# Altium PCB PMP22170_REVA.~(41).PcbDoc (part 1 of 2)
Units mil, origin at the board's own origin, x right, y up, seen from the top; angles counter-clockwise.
Board outline 4950 x 3450 mil, 2 copper layers (Top Layer, Bottom Layer), stack 62 mil thick; 75 components, 28 nets, 158 pads, 70 vias.
Unrouted connection lines stored in the file: 122.
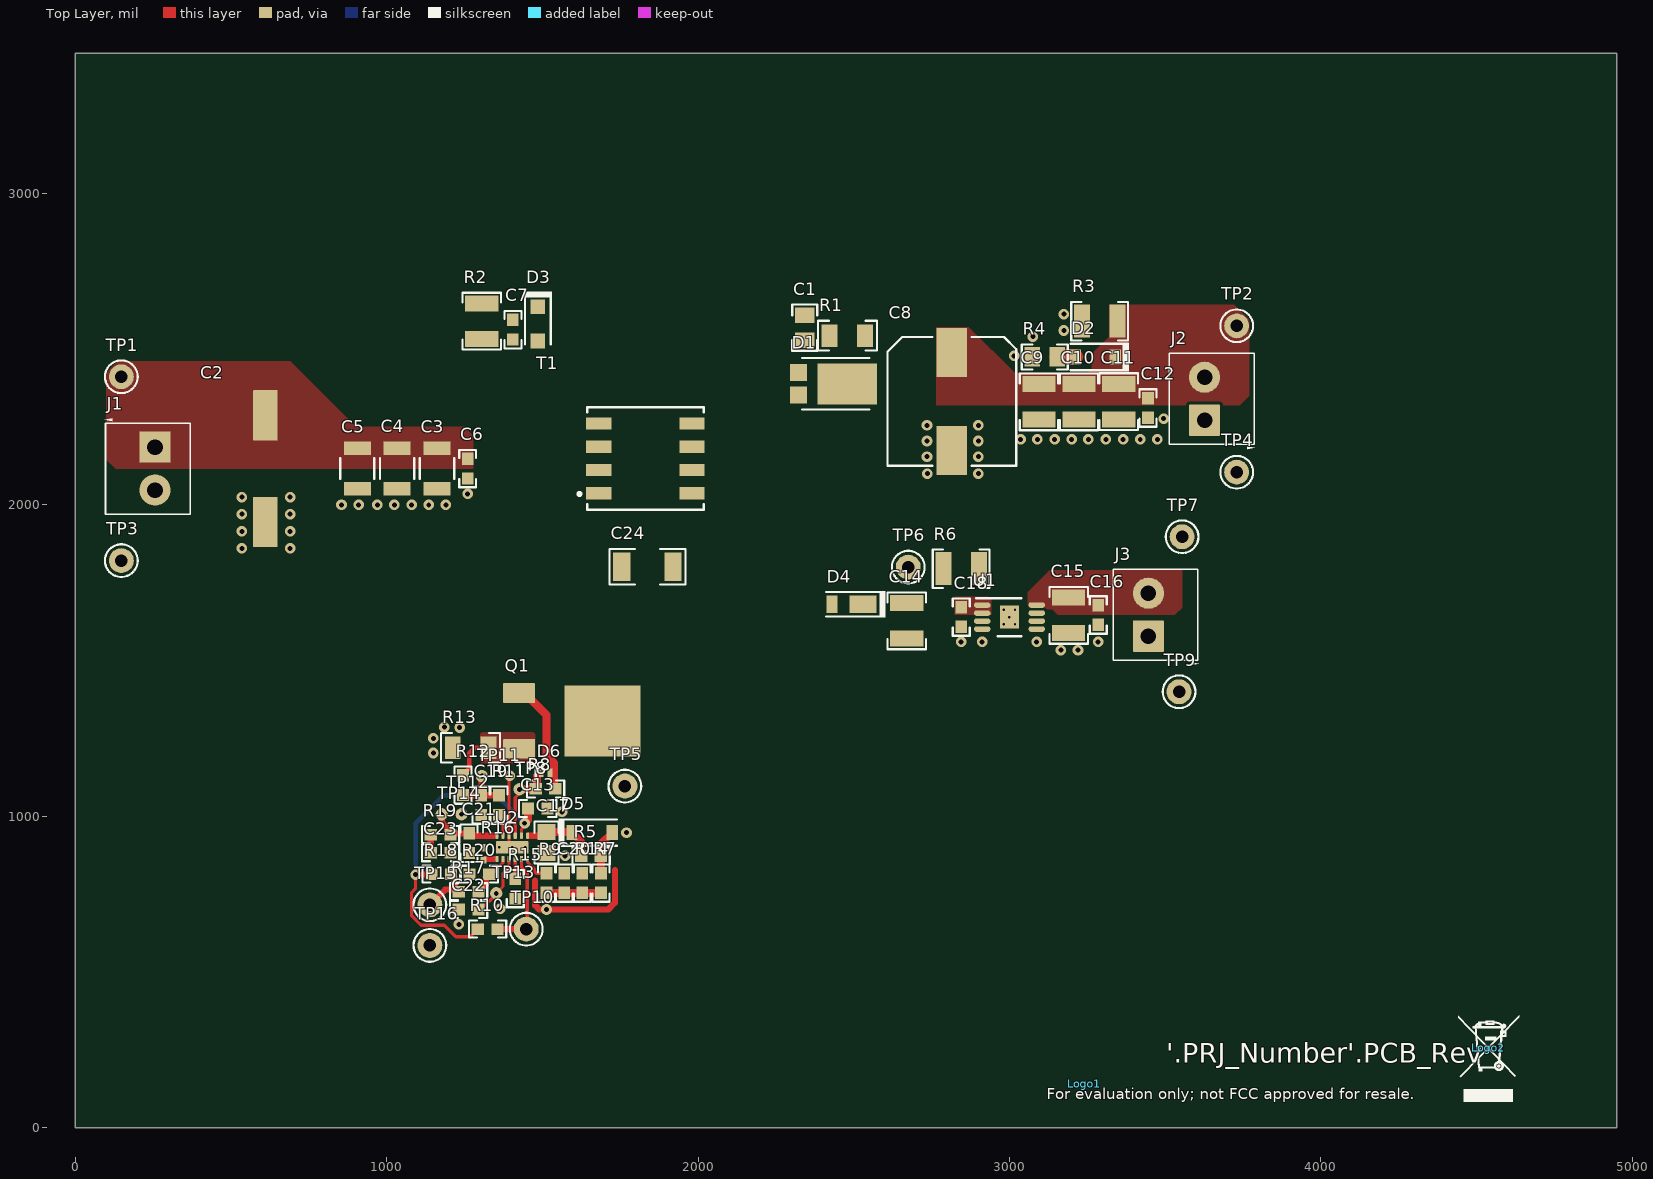
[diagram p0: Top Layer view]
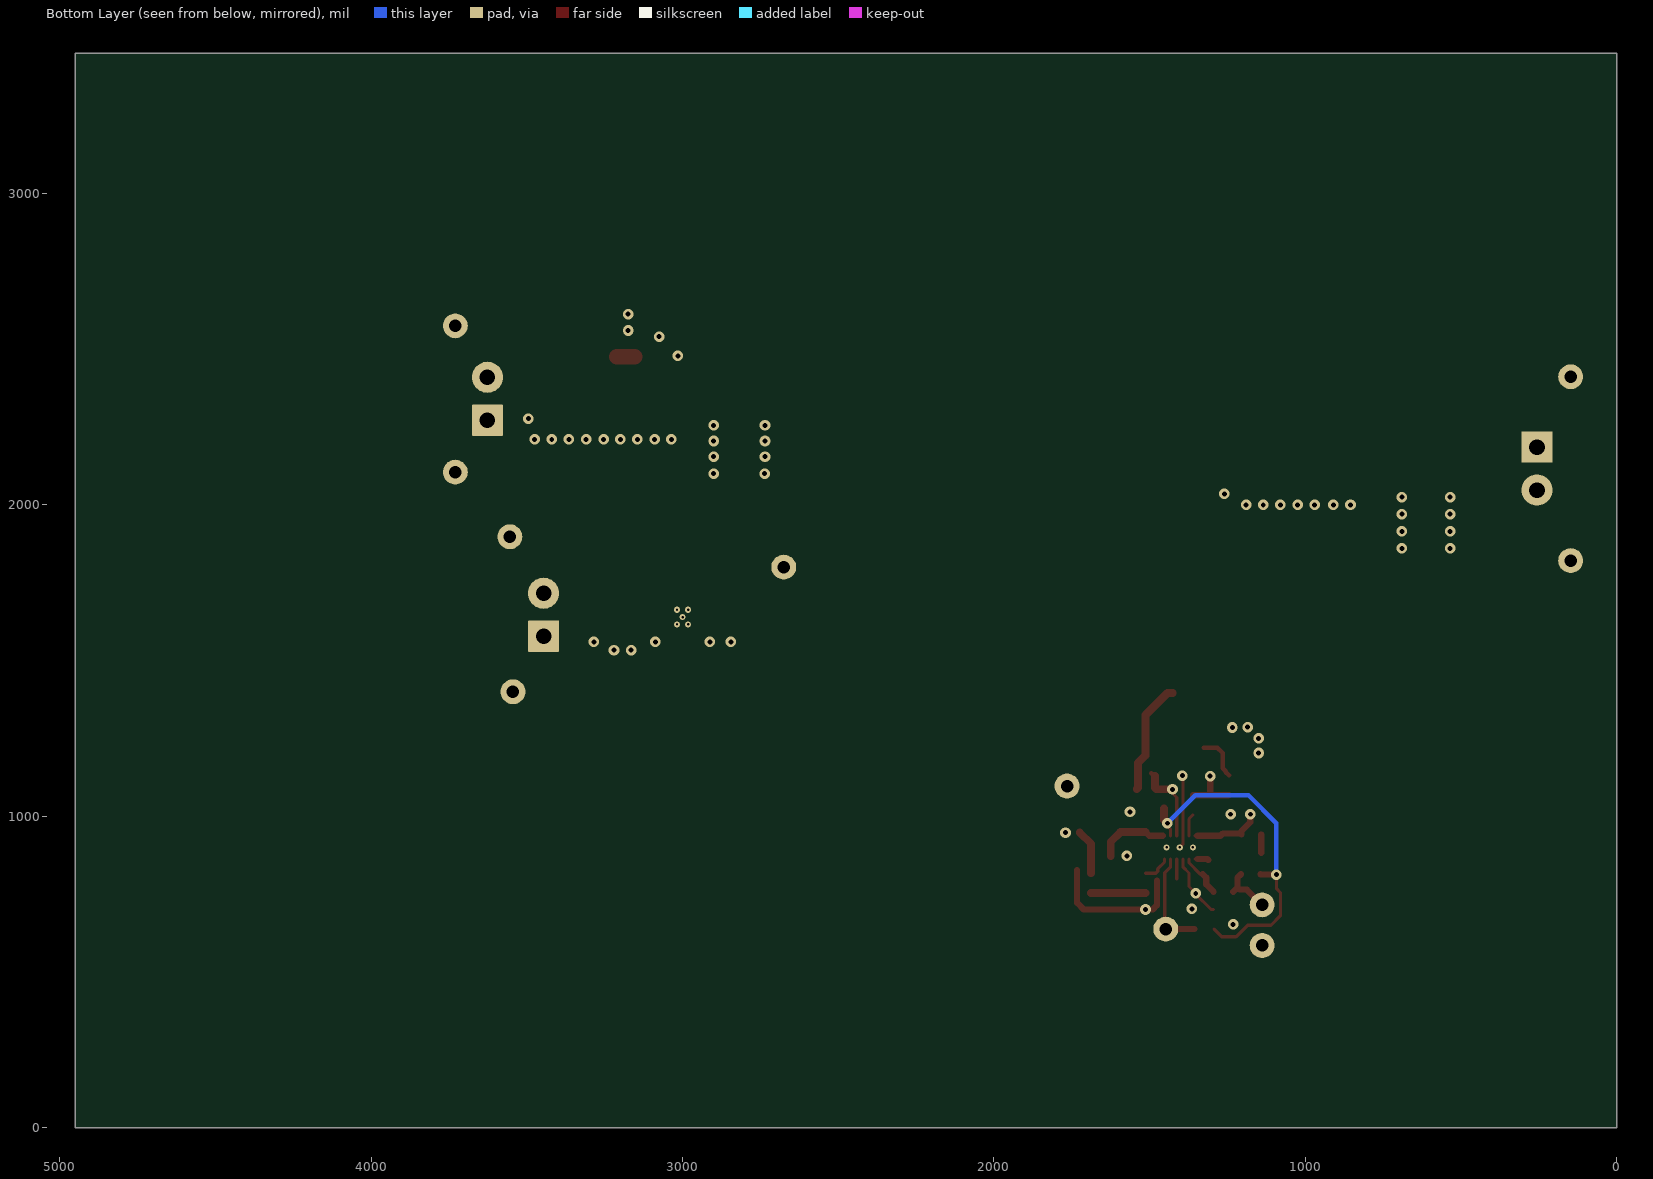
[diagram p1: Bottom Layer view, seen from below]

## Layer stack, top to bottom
Top Solder: solder mask 0.4, Solder Resist, Dk 3.5
Top Layer: signal copper 1.4
Dielectric1: core 59.2, FR-4, Dk 4.8
Bottom Layer: signal copper 1.4
Bottom Solder: solder mask 0.4, Solder Resist, Dk 3.5

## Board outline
0,0 4950,0 4950,3450 0,3450

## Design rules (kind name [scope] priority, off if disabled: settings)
AcuteAngle [All] p1: minimum=4.50000000000000E+0001 checktracksonly=FALSE
AssemblyTestPointUsage [All] p1: valid=2
BoardOutlineClearance BoardOutlineClearance_MountingHoles [OnCopper and InComponentClass('Mounting Holes')] p1: gap=39.37 ignorepadtopadclearanceinfootprint=FALSE
BoardOutlineClearance BoardOutlineClearance_Poly [OnCopper and IsPoly] p2: gap=25 ignorepadtopadclearanceinfootprint=FALSE
BoardOutlineClearance [OnCopper and Not InComponentClass('Logo') and not InComponentClass('FiducialMark') and not InRegion(1000,500,4000,800) and not InPoly] p3: gap=50 ignorepadtopadclearanceinfootprint=FALSE
Clearance Clearance_Keepouts [((IsTrack Or IsArc) And Not InPoly) And IsFree and IsKeepOut vs ((IsTrack Or IsArc) And Not InPoly) And IsFree and IsKeepOut] p1: gap=0 ignorepadtopadclearanceinfootprint=FALSE
Clearance Clearance_Poly [InPolygon] p2: gap=10 ignorepadtopadclearanceinfootprint=TRUE
Clearance Clearance_FiducialMark [IsKeepOut and InComponentClass('FiducialMark') vs IsPad and InComponentClass('FiducialMark')] p3: gap=0 ignorepadtopadclearanceinfootprint=FALSE
Clearance [All] p4: gap=7.87 ignorepadtopadclearanceinfootprint=TRUE
ComponentClearance ComponentClearance_MountingHoles_FiducialMarks [InComponentClass('Mounting Holes') vs InComponentClass('FiducialMark')] p1: gap=50 collisioncheckmode=3 verticalgap=10 showdistances=FALSE
ComponentClearance ComponentClearance_Shunt [InComponentClass('Header') vs InComponentClass('Shunt')] p2: gap=0 collisioncheckmode=3 verticalgap=0 showdistances=FALSE
ComponentClearance ComponentClearance_Logo [InComponentClass('Logo')] p3: gap=50 collisioncheckmode=3 verticalgap=10 showdistances=FALSE
ComponentClearance ComponentClearance_ScrewToNut [(HasFootprint('NY PMS 440 0025 PH')) vs (HasFootprint('Keystone_1902C'))] p4: gap=5 collisioncheckmode=3 verticalgap=10 showdistances=FALSE
ComponentClearance ComponentClearance_MountingHoles [InComponentClass('Mounting Holes')] p5: gap=250 collisioncheckmode=3 verticalgap=100000 showdistances=FALSE
ComponentClearance ComponentClearance_SmallPassives [HasFootprint('0201*') or HasFootprint('0402*') or HasFootprint('0508') or HasFootprint('0603*') or HasFootprint('0612') or HasFootprint('0805*') or HasFootprint('0815*') or HasFootprint('0830*') or HasFootprint('1206*') or HasFootprint('1210*') or HasFootprint('1808*') or HasFootprint('1812*') or HasFootprint('1825*') or HasFootprint('2010*') or HasFootprint('2220*') or HasFootprint('2225*') or HasFootprint('2512*') or HasFootprint('2728*') or HasFootprint('3518*') vs HasFootprint('0201*') or HasFootprint('0402*') or HasFootprint('0508') or HasFootprint('0603*') or HasFootprint('0612') or HasFootprint('0805*') or HasFootprint('0815*') or HasFootprint('0830*') or HasFootprint('1206*') or HasFootprint('1210*') or HasFootprint('1808*') or HasFootprint('1812*') or HasFootprint('1825*') or HasFootprint('2010*') or HasFootprint('2220*') or HasFootprint('2225*') or HasFootprint('2512*') or HasFootprint('2728*') or HasFootprint('3518*')] p6: gap=14.96 collisioncheckmode=3 verticalgap=10 showdistances=FALSE
ComponentClearance ComponentClearance_THtoSMT [IsThruComponent vs IsSMTComponent] p7: gap=30 collisioncheckmode=3 verticalgap=30 showdistances=FALSE
ComponentClearance ComponentClearance_THtoTH [IsThruComponent vs IsThruComponent] p8: gap=30 collisioncheckmode=3 verticalgap=30 showdistances=FALSE
ComponentClearance [All] p9: gap=20 collisioncheckmode=3 verticalgap=10 showdistances=FALSE
DiffPairsRouting [All] p1: maxlimit=100 minlimit=10 mostfreqgap=10 toplayer_minwidth=15 toplayer_maxwidth=15 toplayer_prefwidth=15 bottomlayer_minwidth=15 bottomlayer_maxwidth=15 bottomlayer_prefwidth=15 maxuncoupledlength=1000
FabricationTestPointUsage TestPointUsage [All] p1: valid=2 allowmultiple=FALSE
FabricationTestpoint Testpoint [All] p1: side=3 testpointundercomponent=TRUE minsize=40 maxsize=100 preferedsize=60 minholesize=0 maxholesize=40 preferedholesize=32 testpointgrid=1 allowsidetop=TRUE allowsidebottom=TRUE usegrid=TRUE gridtolerance=0.01
FanoutControl Fanout_LCC [IsLCC] p1: bgadir=Out bgaviamode=Centered fanoutstyle=Auto fanoutdirection=Alternating viagrid=1 // Fanout_LCC (Default Rule)
FanoutControl Fanout_BGA [IsBGA] p2: bgadir=Out bgaviamode=Centered fanoutstyle=Auto fanoutdirection=Alternating viagrid=1 // Fanout_BGA (Default Rule)
FanoutControl Fanout_Default [All] p4: bgadir=Out bgaviamode=Centered fanoutstyle=Auto fanoutdirection=Alternating viagrid=1 // Fanout_Default (Default Rule)
FanoutControl Fanout_Small [(CompPinCount < 5)] p5: bgadir=Out bgaviamode=Centered fanoutstyle=Auto fanoutdirection=OutThenIn viagrid=1 // Fanout_Small (Default Rule)
HoleSize [All] p1: absolutevalues=TRUE maxlimit=251 minlimit=7.87 maxpercent=80.000 minpercent=20.000
MinimumAnnularRing MinimumAnnularRing_ThermalPadVias [IsVia and InAnyComponent] p1: minimumring=5.91
MinimumAnnularRing [All] p2: minimumring=7.87
MinimumSolderMaskSliver MinimumSolderMaskSliver_Logo [InComponentClass('Logo') vs InComponentClass('Logo')] p1: minsoldermaskwidth=0.7
MinimumSolderMaskSliver [All] p2: minsoldermaskwidth=3.94
PlaneClearance [All] p1: clearance=15
PlaneConnect [All] p1: planeconnectstyle=Direct reliefexpansion=10 reliefentries=4 reliefconductorwidth=10 reliefairgap=10
PolygonConnect [All] p1: connectstyle=Direct reliefconductorwidth=10 reliefentries=4 polygonreliefangle="90 Angle" airgapwidth=10
RoutingVias ThermalPadVias [IsVia and InAnyComponent] p1: holewidth=7.87 width=19.68 viastyle="Through Hole" minholewidth=7.87 minwidth=19.68 maxholewidth=12.99 maxwidth=23.62
RoutingVias [All] p2: holewidth=16 width=34 viastyle="Through Hole" minholewidth=7.87 minwidth=26 maxholewidth=40 maxwidth=65
SilkToBoardRegionClearance [Not ((IsComment or IsDesignator) And (Hide <> 'False')) and not InRegion(1000,500,4000,800)] p1:
SilkToSilkClearance SilkToSilkClearance_Pb-FreeLogo [(HasFootprint('Pb-Free_Overlay_Medium') OR HasFootprint('Pb-Free_Overlay_Small')) vs (HasFootprint('Pb-Free_Overlay_Medium') OR HasFootprint('Pb-Free_Overlay_Small'))] p1: silktosilkclearance=0
SilkToSilkClearance [All] p2: silktosilkclearance=0
SilkToSolderMaskClearance SilkToComponentPadClearance [(IsPad or IsFill or IsRegion) and InAnycomponent] p1: minsilkscreentomaskgap=5 clearancetoexposedcopper=TRUE
SilkToSolderMaskClearance "Silk to Solder Mask Opening" [All] p2: minsilkscreentomaskgap=0 clearancetoexposedcopper=FALSE
SolderMaskExpansion [All] p1: expansion=1.97
UnRoutedNet [All] p1: checkbadconnections=TRUE
Width [All] p1: maxlimit=100 minlimit=6 preferedwidth=10 checkconnectedcopper=TRUE
13 further rules are at their usual default settings.

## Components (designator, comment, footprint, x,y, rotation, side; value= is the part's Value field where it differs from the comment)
C1 "Capacitor" 0805_HV 2342.52,2568.9 r270 top value=100pF
C2 "EEH-ZS1H221V" FP-EEHZS1H221P_RADIAL_SMD-MFG 610.24,2116.35 r90 top
C3 "UMK325AB7106KMHT" 1210_280 1161.42,2116.35 r270 top value=10uF
C4 "UMK325AB7106KMHT" 1210_280 1033.46,2116.35 r270 top value=10uF
C5 "UMK325AB7106KMHT" 1210_280 905.51,2116.35 r270 top value=10uF
C6 "Capacitor" 0603 1259.84,2116.35 r270 top value=0.1uF
C7 "Capacitor" 0603 1405.32,2562.52 r90 top value=0.1uF
C8 "EEHZC1E331P" SM_RADIAL_10BMM 2814.96,2332.31 r270 top value=330uF
C9 "TMK325B7226KMHT" 1210_270 3095,2330.98 r270 top value=22uF
C10 "TMK325B7226KMHT" 1210_270 3222.95,2330.98 r270 top value=22uF
C11 "TMK325B7226KMHT" 1210_270 3350.91,2331.16 r270 top value=22uF
C12 "Capacitor" 0603 3445,2311.04 r270 top value=0.1uF
C13 "GCM188R71E105KA64D" 0603 1485,1025 r0 top value=1uF
C14 "Capacitor" 1210_270 2670,1627.56 r270 top value=22uF
C15 "Capacitor" 1210_270 3190,1645 r270 top value=47uF
C16 "Capacitor" 0603 3285,1646.26 r270 top value=0.1uF
C17 "Capacitor" 0805 1513.07,915.85 r270 top value=1uF
C18 "Capacitor" 0603 2845,1639.57 r270 top value=0.1uF
C19 "Capacitor" 0603 1303.03,1035.77 r270 top value=1000pF
C20 "Capacitor" 0603 1570.03,785.34 r90 top value=10pF
C21 "CGA3E2X7R2A222K080AA" 0603 1264.52,913.39 r270 top value=2200pF
C22 "Capacitor" 0603 1263.15,700.46 r180 top value=0.1uF
C23 "CGA3E3X7R1H334K080AB" 0603 1173.03,882.38 r0 top value=0.33uF
C24 "Capacitor" 1808 1837.24,1801.18 r180 top value=1000pF
D1 "PDS4200HQ-13" POWERDI5 2401.22,2388.58 r0 top value=200V
D2 "MMSZ5240B-7-F" SOD-123 3275.59,2475 r180 top value=10V
D3 "DIODE_SCHOTTKY" SOD-123W 1485.32,2581.22 r270 top value=100V
D4 "DFLS1200Q-7" PowerDI123 2479.8,1680.71 r180 top value=200V
D5 "SD103AW-7-F" SOD-123 1659.53,947.38 r0 top value=40V
D6 "DIODE_SCHOTTKY" X1-DFN1006-2 1510,1139.93 r0 top value=30V
J1 "Receptacle_2x1" TERM_BLK_ED555-2DS 255.91,2185.24 r270 top
J2 "Receptacle_2x1" TERM_BLK_ED555-2DS 3626.5,2271.67 r90 top
J3 "Receptacle_2x1" TERM_BLK_ED555-2DS 3446.18,1578.05 r90 top
Logo1 "FCC disclaimer" FCC_disclaimer 3240,140 r0 top
Logo2 "WEEE logo" WEEE_Minimum 4537.4,255.91 r0 top
Q1 "IPD60N10S4L12ATMA1" DPAK 1559.25,1305.91 r0 top value=100V
R1 "CRCW1206100RFKEAHP" 1206 2479.61,2543.31 r0 top value=100
R2 "ERJ14NF1001U" 1210 1305.32,2590 r270 top value=1.00k
R3 "ERJ14NF1001U" 1210 3289.76,2590 r0 top value=1.00k
R4 "CRCW080580R6FKEA" 0805_HV 3113.19,2475 r0 top value=80.6
R5 "Resistor" 0603 1656.22,872.38 r0 top value=0
R6 "ERJ14NF1001U" 1210 2845,1795 r180 top value=1.00k
R7 "CRCW0603100KFKEA" 0603 1688.07,785.34 r90 top value=100k
R8 "Resistor" 0603 1510,1087.68 r180 top value=10.0
R9 "CRCW060371K5FKEA" 0603 1513.03,785.34 r90 top value=71.5k
R10 "CRCW060310K0FKEA" 0603 1324.17,637.38 r0 top value=10.0k
R11 "Resistor" 0603 1360.71,1035.77 r90 top value=0
R12 "Resistor" 0603 1245,1100 r90 top value=100
R13 "ERJ-8BWFR010V" 1206 1269.19,1220 r0 top value=0.010
R14 "CRCW060324K9FKEA" 0603 1628.03,785.34 r270 top value=24.9k
R15 "CRCW060373K2FKEA" 0603 1412.87,767.38 r90 top value=73.2k
R16 "CRCW04020000Z0ED" 0402L 1311.38,878.94 r270 top value=0
R17 "Resistor" 0603 1263.03,757.38 r0 top value=6.04k
R18 "CRCW060320R0FKEA" 0603 1174.98,813.88 r180 top value=20.0
R19 "CRCW06033K01FKEA" 0603 1173.03,940.89 r0 top value=3.01k
R20 "CRCW06031K00FKEA" 0603 1297.6,813.88 r0 top value=1.00k
T1 "" WURTH_750312924 1830.71,2149.24 r90 top
TP1 "5000" Keystone5000 147.64,2411.42 r90 top
TP2 "5000" Keystone5000 3729.76,2575 r90 top
TP3 "5001" Keystone5001 147.64,1820.87 r90 top
TP4 "5001" Keystone5001 3729.76,2105 r90 top
TP5 "5002" Keystone5002 1765,1096.79 r90 top
TP6 "5000" Keystone5000 2675,1800 r0 top
TP7 "5000" Keystone5000 3554.45,1897.6 r90 top
TP8 "TP_SM_1MM" TP_SM_1MM 1426.46,1086.52 r180 top
TP9 "5001" Keystone5001 3544.61,1399.68 r90 top
TP10 "5000" Keystone5000 1448.03,637.38 r90 top
TP11 "TP_SM_1MM" TP_SM_1MM 1305.47,1128.84 r0 top
TP12 "TP_SM_1MM" TP_SM_1MM 1240,1006.3 r0 top
TP13 "TP_SM_1MM" TP_SM_1MM 1351.73,752.38 r90 top
TP14 "TP_SM_1MM" TP_SM_1MM 1176.67,1006.3 r90 top
TP15 "5003" Keystone5003 1138.58,715.45 r90 top
TP16 "5001" Keystone5001 1138.58,585 r90 top
U1 "TPS7B8250QDGNRQ1" DGN0008D_N 3000,1639.57 r0 top
U2 "LM5155QDSSTQ1" DSS0012C 1403.03,899.98 r270 top

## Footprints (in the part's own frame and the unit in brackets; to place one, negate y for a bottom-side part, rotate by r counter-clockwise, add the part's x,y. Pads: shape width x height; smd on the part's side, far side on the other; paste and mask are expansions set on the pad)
0402L [mm] "0402 from SM-752 data"
  rect 0.6x0.5 smd: 1(-0.5,0) 2(0.5,0)
  body extent -0.55,-0.3 0.55,0.3, height 0.6
0603 [mm] "0603 from SM-752 data"
  rect 1x0.95 smd: 1(-0.8,0) 2(0.8,0)
  silkscreen extent -1.52,-0.69 1.52,0.69, body extent -0.87,-0.47 0.87,0.47, height 1
0805 [mm] "0805 from SM-752 data"
  rect 1.3x1.5 smd: 1(-0.85,0) 2(0.85,0)
  silkscreen extent -1.72,-0.97 1.72,0.97, body extent -1.1,-0.72 1.1,0.72, height 1.45
0805_HV [mil] "0805 with 30mil clearance between pads"
  rect 50x63 smd: 1(-40,0) 2(40,0)
  silkscreen extent -74,-40 74,40, body extent -43,-29 43,29, height 57
1206 [mm] "1206 from SM-752 data"
  rect 1.3x1.85 smd: 1(-1.45,0) 2(1.45,0)
  silkscreen extent -2.4,-1.21 2.4,1.21, body extent -1.7,-0.9 1.7,0.9, height 1.35
1210 [mm] "1210 from SM-752 data"
  rect 1.3x2.7 smd: 1(-1.45,0) 2(1.45,0)
  silkscreen extent -2.32,-1.57 2.32,1.57, body extent -1.7,-1.35 1.7,1.35, height 1.35
1210_270 [mm] "1210"
  rect 1.3x2.7 smd: 1(-1.45,0) 2(1.45,0)
  silkscreen extent -2.32,-1.57 2.32,1.57, body extent -1.7,-1.35 1.7,1.35, height 2.7
1210_280 [mm] "SMD, 2-Leads, Body 3.6x2.8mm, Height 2.8mm"
  rect 1.1x2.2 smd: 1(-1.65,0) 2(1.65,0)
  silkscreen extent -0.84,-1.4 0.84,1.4, body extent -1.8,-1.4 1.8,1.4, height 2.8
1808 [mm] "Chip Capacitor, Body 4.6x2.0mm, IPC Medium Density"
  rect 1.4x2.3 smd: 1(-2.1,0) 2(2.1,0)
  silkscreen extent -3.1,-1.45 3.1,1.45, body extent -2.47,-1.2 2.47,1.2, height 2.03
DGN0008D_N [mm] "TSOP, 8-Leads, Body 3x3mm, Pitch 0.65mm, Thermal Pad 1.89x1.57mm, IPC Medium Density"
  rrect100% 1.35x0.45 smd: 1(-2.225,0.975) 2(-2.225,0.325) 3(-2.225,-0.325) 4(-2.225,-0.975) 5(2.225,-0.975) 6(2.225,-0.325) 7(2.225,0.325) 8(2.225,0.975)
  rrect6% 1.57x1.89 smd: 9(0,0)
  silkscreen extent -2.73,-1.55 0.95,1.55, body extent -2.46,-1.5 2.46,1.5, height 1.1
DPAK [mm] "D-PAK, 3-Pads, Body 6.22x6.73mm (max), TO-252AA using nominal STEP model"
  rrect6% 2.6x1.6 smd: 1(-3.4,2.28) 3(-3.4,-2.28)
  rrect2% 6.2x5.8 smd paste-3: 2(3.4,0)
  body extent -3.86,-3.29 5.84,3.29, height 2.48
DSS0012C [mm] "WSON-12"
  rrect40% 0.5x0.25 smd: 1(-0.95,1.25) 2(-0.95,0.75) 3(-0.95,0.25) 4(-0.95,-0.25) 5(-0.95,-0.75) 6(-0.95,-1.25) 7(0.95,-1.25) 8(0.95,-0.75) 9(0.95,-0.25) 10(0.95,0.25) 11(0.95,0.75) 12(0.95,1.25)
  rrect11% 0.95x1.17 on Top Paste: 13(0,0.685) 13(0,-0.685)
  rrect11% 1x2.65 smd paste-0.5: 13(0,0)
  body extent -1,-1.5 1,1.5, height 0.81
FCC_disclaimer [mil]
FP-EEHZS1H221P_RADIAL_SMD-MFG [mm]
  rrect5% 4.1x2 smd paste+0 mask+0: 1(-4.35,0) 2(4.35,0)
  body extent -6.65,-5.5 6.65,5.5, height 0.25
Keystone5000 [mil] "For Keystone 500x miniature loop terminals"
  round 80 hole 40: 1(0,0)
  silkscreen extent -52,-52 52,52, body extent -49,-49 49,49, height 182
Keystone5001 [mil] "For Keystone 500x miniature loop terminals"
  round 80 hole 40: 1(0,0)
  silkscreen extent -52,-52 52,52, body extent -49,-49 49,49, height 182
Keystone5002 [mil] "For Keystone 500x miniature loop terminals"
  round 80 hole 40: 1(0,0)
  silkscreen extent -52,-52 52,52, body extent -49,-49 49,49, height 182
Keystone5003 [mil] "For Keystone 500x miniature loop terminals"
  round 80 hole 40: 1(0,0)
  silkscreen extent -52,-52 52,52, body extent -49,-49 49,49, height 182
POWERDI5 [mm] "Diodes Inc recommended land pattern, ap02001.pdf rev 60"
  rect 1.4x1.39 smd: 1(-1.991,0.92) 2(-1.991,-0.92)
  rect 4.86x3.36 smd: 3(1.991,0)
  silkscreen extent -1.7,-2.1 3.8,2.1, body extent -2.27,-2.03 4.33,2.03, height 1.17
PowerDI123 [mm] "Diodes Inc recommended land pattern, document number DS30628 Rev. 6-2"
  rect 2.2x1.4 smd: 1(-1.275,0)
  rect 0.9x1.4 smd: 2(1.275,0)
  silkscreen extent -3.1,-1.09 1.76,1.09, body extent -2.38,-0.97 1.52,0.96, height 1
SM_RADIAL_10BMM [mm] "Nichicon 10x10"
  rect 4x2.5 smd: 1(-4,0) 2(4,0)
  silkscreen extent -5.25,-5.25 5.25,5.25, body extent -5.25,-5.25 5.25,5.25, height 10.5
SOD-123 [mm] "On Semi recommended land pattern"
  rect 0.915x1.22 smd: 1(-1.637,0) 2(1.637,0)
  silkscreen extent -2.74,-1.17 2.03,1.17, body extent -1.93,-0.9 1.93,0.9, height 1.35
SOD-123W [mm] "NXP recommended land pattern"
  rect 1.2x1.2 smd paste-0.05: 1(-1.4,0) 2(1.4,0)
  silkscreen extent -2.64,-1.14 1.68,1.14, body extent -1.85,-0.95 1.85,0.95, height 1.1
TERM_BLK_ED555-2DS [mil]
  rrect4% 100x100 hole 50: 1(0,0)
  round 100 hole 50: 2(138,0)
  silkscreen extent -93,-161 215,113, body extent -69,-150 207,106, height 323
TP_SM_1MM [mm] "1mm Test Point, SMT"
  round 1 smd paste-0.5: 1(0,0)
WEEE_Minimum [mil] "WEEElie bin"
  silkscreen extent -95,-172 99,104
WURTH_750312924 [mm] "SMD, 8-Leads, Body 9.5x8.35mm, Pitch 1.9mm"
  rect 1x2.06 smd: 1(-2.85,3.8) 2(-0.95,3.8) 3(0.95,3.8) 4(2.85,3.8) 5(2.85,-3.8) 6(0.95,-3.8) 7(-0.95,-3.8) 8(-2.85,-3.8)
  silkscreen extent -4.18,-4.75 4.18,5.5, body extent -4.18,-4.75 4.18,4.75, height 6.35
X1-DFN1006-2 [mm] "DIODES, INC"
  rect 0.4x0.7 smd: 1(-0.35,0) 2(0.35,0)
  silkscreen extent -0.8,-0.35 -0.8,0.35, body extent -0.54,-0.34 0.54,0.34, height 0.53

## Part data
C1: library part CMP-0008236-2, "CAP, CERM, 100 pF, 250 V, +/- 5%, C0G/NP0, 0805", Cap_Case=0805, Manufacturer=MuRata, PartNumber=GRM21A5C2E101JW01D, Supplier Part Number 1=490-5542-1-ND, TempCo=C0G/NP0, Tolerance_%=5%, Value1=Unknown, Value2=250V, ValueDisplayed=100pF
C2: library part CMP-0087071-1, "220µF 50V Aluminum Polymer Capacitor Radial, Can - SMD 13 mOhm 4000 Hrs @ 125°C", Manufacturer=Panasonic, Tolerance_%=20%
C3 C4 C5: library part CMP-0009258-2, "CAP, CERM, 10 uF, 50 V, +/- 10%, X7R, AEC-Q200 Grade 1, 1210", Cap_Case=1210, Manufacturer="Taiyo Yuden", Supplier Part Number 1=587-4326-1-ND, TempCo=X7R, Tolerance_%=10%, Value1=Unknown, Value2=50V, ValueDisplayed=10uF
C6 C7 C12: library part CMP-0007144-4, "CAP, CERM, 0.1 uF, 50 V, +/- 10%, X7R, 0603", Cap_Case=0603, Manufacturer=MuRata, PartNumber=GCM188R71H104KA57D, Supplier Part Number 1=490-4779-1-ND, TempCo=X7R, Tolerance_%=10%, Value1="0.02 ohm", Value2=50V, ValueDisplayed=0.1uF
C8: library part CMP-0012593-3, "CAP, Polymer Hybrid, 330 uF, 25 V, +/- 20%, 20 mohm, 10x10 SMD", Manufacturer=Panasonic, Supplier Part Number 1=P15459CT-ND, Tolerance_%=20%, Value1="20 ohm", Value2=25V, ValueDisplayed=330uF
C9 C10 C11: library part CMP-0009255-2, "CAP, CERM, 22 uF, 25 V, +/- 10%, X7R, AEC-Q200 Grade 1, 1210", Cap_Case=1210, Manufacturer="Taiyo Yuden", Supplier Part Number 1=587-4337-1-ND, TempCo=X7R, Tolerance_%=10%, Value1=Unknown, Value2=25V, ValueDisplayed=22uF
C13: library part CMP-0007139-4, "CAP, CERM, 1 uF, 25 V, +/- 10%, X7R, AEC-Q200 Grade 1, 0603", Cap_Case=0603, Manufacturer=MuRata, Supplier Part Number 1=490-10673-1-ND, TempCo=X7R, Tolerance_%=10%, Value1=Unknown, Value2=25V, ValueDisplayed=1uF
C14: library part CMP-0009224-2, "CAP, CERM, 22 uF, 25 V, +/- 10%, X7R, 1210", Cap_Case=1210, Manufacturer=MuRata, PartNumber=GRM32ER71E226KE15L, Supplier Part Number 1=490-5313-1-ND, TempCo=X7R, Tolerance_%=10%, Value1=Unknown, Value2=25V, ValueDisplayed=22uF
C15: library part CMP-0009220-2, "CAP, CERM, 47 uF, 10 V, +/- 10%, X7R, 1210", Cap_Case=1210, Manufacturer=MuRata, PartNumber=GRM32ER71A476KE15L, Supplier Part Number 1=490-5312-1-ND, TempCo=X7R, Tolerance_%=10%, Value1=Unknown, Value2=10V, ValueDisplayed=47uF
C16 C18 C22: library part CMP-0007378-5, "CAP, CERM, 0.1 uF, 16 V, +/- 10%, X7R, 0603", Cap_Case=0603, Manufacturer=MuRata, PartNumber=GRM188R71C104KA01D, Supplier Part Number 1=490-1532-1-ND, TempCo=X7R, Tolerance_%=10%, Value1=Unknown, Value2=16V, ValueDisplayed=0.1uF
C17: library part CMP-0008350-2, "CAP, CERM, 1 uF, 50 V, +/- 10%, X7R, 0805", Cap_Case=0805, Manufacturer=MuRata, PartNumber=GRM21BR71H105KA12L, Supplier Part Number 1=490-4736-1-ND, TempCo=X7R, Tolerance_%=10%, Value1=Unknown, Value2=50V, ValueDisplayed=1uF
C19: library part CMP-0007402-4, "CAP, CERM, 1000 pF, 25 V, +/- 10%, X7R, 0603", Cap_Case=0603, Manufacturer=MuRata, PartNumber=GRM188R71E102KA01D, Supplier Part Number 1=GRM188R71E102KA01D-ND, TempCo=X7R, Tolerance_%=10%, Value1=Unknown, Value2=25V, ValueDisplayed=1000pF
C20: library part CMP-0007170-4, "CAP, CERM, 10 pF, 50 V, +/- 5%, C0G/NP0, 0603", Cap_Case=0603, Manufacturer=MuRata, PartNumber=GRM1885C1H100JA01D, Supplier Part Number 1=490-1403-1-ND, TempCo=C0G/NP0, Tolerance_%=5%, Value1=Unknown, Value2=50V, ValueDisplayed=10pF
C21: library part CMP-0007085-4, "CAP, CERM, 2200 pF, 100 V, +/- 10%, X7R, AEC-Q200 Grade 1, 0603", Cap_Case=0603, Manufacturer=TDK, Supplier Part Number 1=445-5808-1-ND, TempCo=X7R, Tolerance_%=10%, Value1="0.923948 ohm", Value2=100V, ValueDisplayed=2200pF
C23: library part CMP-0007095-4, "CAP, CERM, 0.33 uF, 50 V, +/- 10%, X7R, AEC-Q200 Grade 1, 0603", Cap_Case=0603, Manufacturer=TDK, Supplier Part Number 1=445-174426-1-ND, TempCo=X7R, Tolerance_%=10%, Value1="0.01584 ohm", Value2=50V, ValueDisplayed=0.33uF
C24: library part CMP-0009436-2, "CAP, CERM, 1000 pF, 2000 V, +/- 10%, X7R, 1808", Cap_Case=1808, Manufacturer=MuRata, PartNumber=GR442QR73D102KW01L, Supplier Part Number 1=490-8145-1-ND, TempCo=X7R, Tolerance_%=10%, Value1=Unknown, Value2=2000V, ValueDisplayed=1000pF
D1: library part CMP-0081019-2, "Diode, Schottky, 200 V, 4 A, AEC-Q101, PowerDI5", Manufacturer="Diodes Inc.", Value1=4A, Value2=0.84V
D2: library part CMP-0005749-3, "Diode, Zener, 10 V, 500 mW, SOD-123", Manufacturer="Diodes Inc.", Power_W=500mW, Value1=0.5W
D3: library part CMP-0028782-2, "Diode, Schottky, 100 V, 1 A, AEC-Q101, SOD-123W", Manufacturer=Nexperia, PartNumber=PMEG10010ELRX, Value1=1A, Value2=0.77V
D4: library part CMP-0028517-2, "Diode, Schottky, 200 V, 1 A, PowerDI123", Manufacturer="Diodes Inc.", Value1=1A, Value2=0.85V
D5: library part CMP-0028543-1, "Diode, Schottky, 40 V, 0.35 A, SOD-123", Manufacturer="Diodes Inc.", Supplier Part Number 1=SD103-AWDICT-ND, Value1=0.35A, Value2=0.55V
D6: library part CMP-0076931-2, "Diode, Schottky, 30 V, 0.2 A, 1.00x0.50x0.60mm", Manufacturer="Diodes Inc.", PartNumber=BAT54LP-7, Value1=0.2A, Value2=1V
J1 J2 J3: library part CMP-0074913-1, "Terminal Block, 3.5mm Pitch, 2x1, TH", Color=Grey, Current_A=6A, Manufacturer="On-Shore Technology", PartNumber=ED555/2DS, Supplier Part Number 1=ED1514-ND, Voltage_V=150V
Logo1: library part CMP-0074847-1, "FCC_disclaimer"
Logo2: library part CMP-0074769-1
Q1: library part CMP-0080670-2, "MOSFET, N-CH, 100 V, 60 A, AEC-Q101, DPAK", Alternate Manufacturer=None, Manufacturer="Infineon Technologies", Supplier Part Number 1=IPD60N10S4L12ATMA1CT-ND, Value1="0.015 ohm", Value2="38 nC"
R1: library part CMP-0016570-3, "RES, 100, 1%, 0.5 W, AEC-Q200 Grade 0, 1206", Manufacturer=Vishay-Dale, Power_W=500mW, Supplier Part Number 1=541-100UCT-ND, TempCo="100 ppm/C", Tolerance_%=1%, Value2=0.5W, Value_Code=100R, ValueDisplayed=100
R2 R3 R6: library part CMP-0015030-3, "RES, 1.00 k, 1%, 0.5 W, AEC-Q200 Grade 0, 1210", Manufacturer=Panasonic, Power_W=500mW, Supplier Part Number 1=P1.00KAACT-ND, TempCo="100 ppm/C", Tolerance_%=1%, Value2=0.5W, Value_Code=1k00, ValueDisplayed=1.00k
R4: library part CMP-0021452-3, "RES, 80.6, 1%, 0.125 W, AEC-Q200 Grade 0, 0805", Manufacturer=Vishay-Dale, Power_W=125mW, Supplier Part Number 1=541-80.6CCT-ND, TempCo="100 ppm/C", Tolerance_%=1%, Value2=0.125W, Value_Code=80R6, ValueDisplayed=80.6
R5 R11: library part CMP-0025697-4, "RES, 0, 5%, 0.1 W, AEC-Q200 Grade 0, 0603", Manufacturer=Vishay-Dale, PartNumber=CRCW06030000Z0EA, Power_W=100mW, Supplier Part Number 1=541-0.0GCT-ND, TempCo="200 ppm/C", Tolerance_%=5%, Value2=0.1W, Value_Code=0000, ValueDisplayed=0
R7: library part CMP-0021990-4, "RES, 100 k, 1%, 0.1 W, AEC-Q200 Grade 0, 0603", Manufacturer=Vishay-Dale, Power_W=100mW, Supplier Part Number 1=541-100KHCT-ND, TempCo="100 ppm/C", Tolerance_%=1%, Value2=0.1W, Value_Code=100k
R8: library part CMP-0022003-4, "RES, 10.0, 1%, 0.1 W, AEC-Q200 Grade 0, 0603", Manufacturer=Vishay-Dale, PartNumber=CRCW060310R0FKEA, Power_W=100mW, Supplier Part Number 1=541-10.0HCT-ND, TempCo="100 ppm/C", Tolerance_%=1%, Value2=0.1W, Value_Code=10R0, ValueDisplayed=10.0
R9: library part CMP-0022581-4, "RES, 71.5 k, 1%, 0.1 W, AEC-Q200 Grade 0, 0603", Manufacturer=Vishay-Dale, Power_W=100mW, Supplier Part Number 1=541-71.5KHCT-ND, TempCo="100 ppm/C", Tolerance_%=1%, Value2=0.1W, Value_Code=71k5, ValueDisplayed=71.5k
R10: library part CMP-0021998-4, "RES, 10.0 k, 1%, 0.1 W, AEC-Q200 Grade 0, 0603", Manufacturer=Vishay-Dale, Power_W=100mW, Supplier Part Number 1=541-10.0KHCT-ND, TempCo="100 ppm/C", Tolerance_%=1%, Value2=0.1W, Value_Code=10k0, ValueDisplayed=10.0k
R12: library part CMP-0021991-4, "RES, 100, 1%, 0.1 W, AEC-Q200 Grade 0, 0603", Manufacturer=Vishay-Dale, PartNumber=CRCW0603100RFKEA, Power_W=100mW, Supplier Part Number 1=541-100HCT-ND, TempCo="100 ppm/C", Tolerance_%=1%, Value2=0.1W, Value_Code=100R, ValueDisplayed=100
R13: library part CMP-0750151-1, "RES, 0.010, 1%, 1 W, AEC-Q200 Grade 0, 1206", Manufacturer=Panasonic, Power_W=1W, TempCo="200 ppm/C", Tolerance_%=1%, Value_Code=R010, ValueDisplayed=0.010
R14: library part CMP-0022237-4, "RES, 24.9 k, 1%, 0.1 W, AEC-Q200 Grade 0, 0603", Manufacturer=Vishay-Dale, Power_W=100mW, Supplier Part Number 1=541-24.9KHCT-ND, TempCo="100 ppm/C", Tolerance_%=1%, Value2=0.1W, Value_Code=24k9, ValueDisplayed=24.9k
R15: library part CMP-0022585-4, "RES, 73.2 k, 1%, 0.1 W, AEC-Q200 Grade 0, 0603", Manufacturer=Vishay-Dale, Power_W=100mW, Supplier Part Number 1=541-73.2KHCT-ND, TempCo="100 ppm/C", Tolerance_%=1%, Value2=0.1W, Value_Code=73k2, ValueDisplayed=73.2k
R16: library part CMP-0026822-3, "RES, 0, 5%, 0.063 W, AEC-Q200 Grade 0, 0402", Manufacturer=Vishay-Dale, Power_W=63mW, Supplier Part Number 1=541-0.0JCT-ND, TempCo="200 ppm/C", Tolerance_%=5%, Value2=0.063W, Value_Code=0000, ValueDisplayed=0
R17: library part CMP-0022558-4, "RES, 6.04 k, 1%, 0.1 W, AEC-Q200 Grade 0, 0603", Manufacturer=Vishay-Dale, PartNumber=CRCW06036K04FKEA, Power_W=100mW, Supplier Part Number 1=541-6.04KHCT-ND, TempCo="100 ppm/C", Tolerance_%=1%, Value2=0.1W, Value_Code=6k04, ValueDisplayed=6.04k
R18: library part CMP-0022206-4, "RES, 20.0, 1%, 0.1 W, AEC-Q200 Grade 0, 0603", Manufacturer=Vishay-Dale, Power_W=100mW, Supplier Part Number 1=541-20.0HCT-ND, TempCo="100 ppm/C", Tolerance_%=1%, Value2=0.1W, Value_Code=20R0, ValueDisplayed=20.0
R19: library part CMP-0022371-4, "RES, 3.01 k, 1%, 0.1 W, AEC-Q200 Grade 0, 0603", Manufacturer=Vishay-Dale, Power_W=100mW, Supplier Part Number 1=541-3.01KHCT-ND, TempCo="100 ppm/C", Tolerance_%=1%, Value2=0.1W, Value_Code=3k01, ValueDisplayed=3.01k
R20: library part CMP-0022109-5, "RES, 1.00 k, 1%, 0.1 W, AEC-Q200 Grade 0, 0603", Manufacturer=Vishay-Dale, Power_W=100mW, Supplier Part Number 1=541-1.00KHCT-ND, TempCo="100 ppm/C", Tolerance_%=1%, Value2=0.1W, Value_Code=1k00, ValueDisplayed=1.00k
T1: library part CMP-0030533-1, "Transformer, 7 uH, SMT", Manufacturer="Wurth Elektronik", PartNumber=TBD
TP1 TP2 TP6 TP7 TP10: library part CMP-0055137-1, "Test Point, Miniature, Red, TH", Color=Red, Manufacturer=Keystone, Supplier Part Number 1=36-5000-ND
TP3 TP4 TP9 TP16: library part CMP-0055138-1, "Test Point, Miniature, Black, TH", Color=Black, Manufacturer=Keystone, Supplier Part Number 1=36-5001-ND
TP5: library part CMP-0055139-1, "Test Point, Miniature, White, TH", Color=White, Manufacturer=Keystone, Supplier Part Number 1=36-5002-ND
TP8 TP11 TP12 TP13 TP14: library part CMP-0003825-1, "1mm Test Point, SMT", Manufacturer=Any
